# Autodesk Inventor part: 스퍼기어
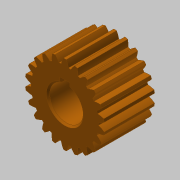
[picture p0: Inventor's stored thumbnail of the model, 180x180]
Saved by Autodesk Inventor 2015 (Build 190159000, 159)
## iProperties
Created: 2019-03
Part Number: 스퍼기어
Material: 강철
Document SubType Name: Modeling
Designer: mduedu
Categories: <?xml version="1.0" encoding="UTF-16"?> <MemberInstance><Categories><FamilyTemplate><FamilyTemplateParameter ValueType="xs:double" Id="1" ObjectReferenceKey="da
Density: 1 g/cm^3
Appearance: 주황색
CustomPartVersion: 1
Author: mduedu
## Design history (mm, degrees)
sketch "Sketch1"
  geometry: C1 r 23.6 at (0, 0)
  constraints: 1 centre point
  dimensions: "d0" = 47.2 diameter of C1 (= da_da)
extrude "Extrusion1" new body sketch "Sketch1" distance "d1" = 30 (= da_b); taper "d2" = 0 deg
workplane "Work Plane2"
sketch "Sketch2"
  geometry: C1 r 23.6 at (0, 0) reference; C2 r 22 at (0, 0)
  constraints: 1 centre point, 1 coincident
  dimensions: "d3" = 44 diameter of C2 (= da_dw)
feature "피치 지름" sketch "Sketch2" dims "d4" = 10, "d5" = 0
workplane "Work Plane8"
workplane "Work Plane9"
feature "스퍼 기어" dims "da_b" = 30, "da_d" = 44, "da_aw" = 44, "da_da" = 47.2, "da_df" = 40.172, "da_dw" = 44, angle "da_beta" = 0 deg, "da_lefttooth" = 0, "da_righttooth" = 0
sketch "스케치3"
  geometry: L1 (-3, 9.539)-(3, 9.539); L2 (3, 9.539)-(3, 12.8); L3 (3, 12.8)-(-3, 12.8); L4 (-3, 12.8)-(-3, 9.539); A1 r 10 centre (0, 0) between (-3, 9.539) and (3, 9.539); 1 further point
  constraints: 8 end point, 2 parallel, 2 point on circle, 1 centre point, 1 coincident, 1 horizontal, 1 perpendicular
  dimensions: "d49" = 20 diameter of A1; "d50" = 6 distance of L2.end L3.end; "d51" = 22.8 dimension on A1 L3
extrude "돌출2" cut sketch "스케치3" stored distance "d52" = 10; taper "d53" = 0 deg
chamfer "모따기1" distance "d54" = 1; stored, may be unused: second distance "d55" = 2, angle "d56" = 45 deg
body "Solid1"
body "Srf1"
other parameters: "d16" = 44 (= da_aw), "d17" = 0, "d34" = 1.428 (computed from da_z), "d39" = 0, "d41" = 0, "d43" = 44 (= da_aw), "d46" = 44 (= da_aw), "d47" = 0, "d48" = 0
